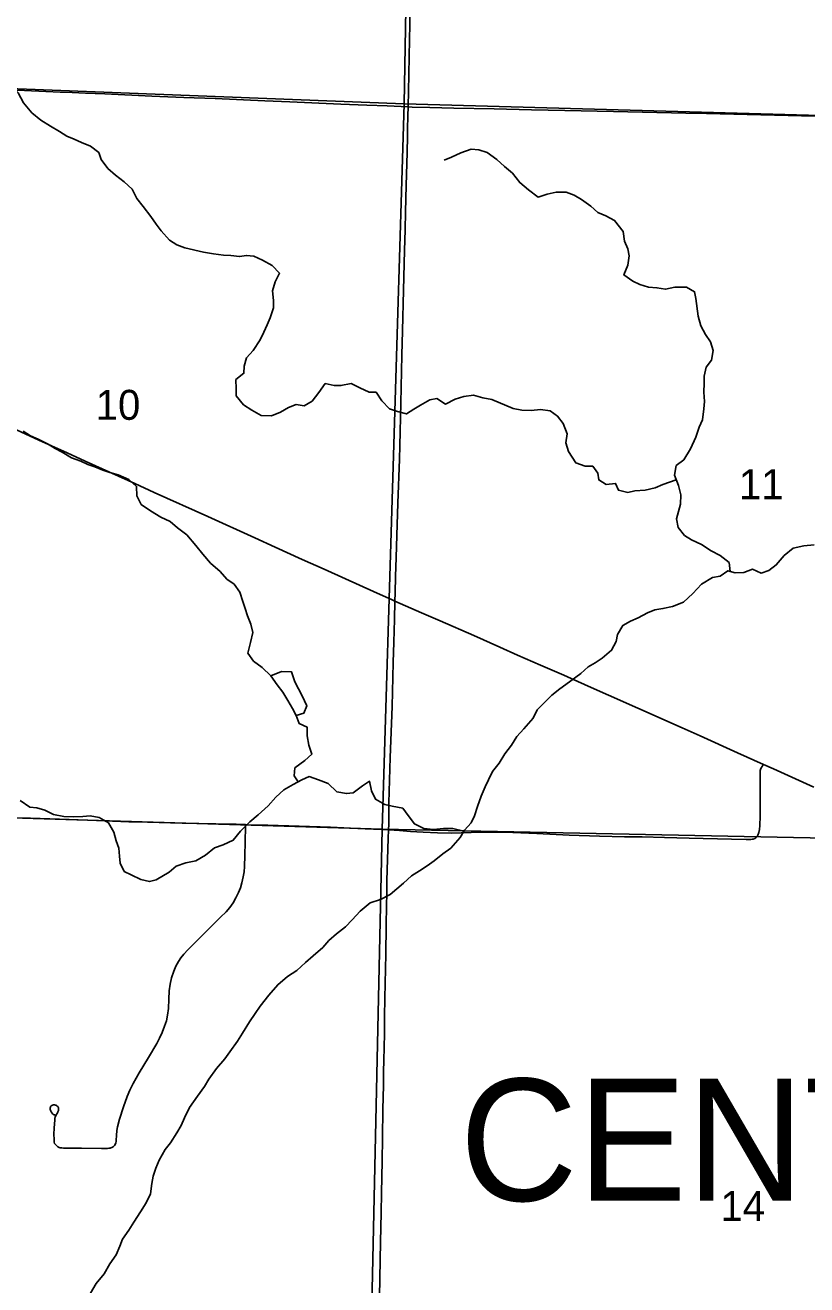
# Model space of a CAD drawing. Extents: x 0 to 34, y 0 to 22.
# Drawn here: x 3.245 to 4.336, y 17.97 to 19.729 of the extents above; entities that cross this region are included whole.
import ezdxf

# ---------------------------------------------------------------- set-up
doc = ezdxf.new("R2010")
doc.units = 0
for name, color, linetype in [('GM_X_Corporation', 7, 'Continuous'), ('GM_X_Minor_Lake', 7, 'Continuous'), ('GM_X_Minor_River', 7, 'Continuous'), ('GM_X_Section_Text', 7, 'Continuous'), ('GM_X_State_Route', 7, 'Continuous'), ('GM_X_Township_Road', 7, 'Continuous'), ('GM_X_Township_Text', 7, 'Continuous')]:
    doc.layers.add(name, color=color, linetype=linetype)

msp = doc.modelspace()

# ---------------------------------------------------------------- linework, layer by layer
at = {"layer": 'GM_X_Corporation'}
for points in [[(2.7647, 20.6164), (2.8121, 20.6157), (3.7914, 20.5987), (3.7742, 19.6197), (2.7554, 19.6589)], [(3.7914, 20.5987), (3.8107, 20.5986), (4.8123, 20.5837), (4.829, 20.5833), (4.8036, 19.5906), (3.7742, 19.6197)], [(2.7554, 19.6589), (3.7742, 19.6197), (3.7435, 18.6067), (2.7385, 18.6376)], [(3.7742, 19.6197), (4.8036, 19.5906), (4.7775, 18.5857), (3.7435, 18.6067)], [(2.7385, 18.6376), (3.7435, 18.6067), (3.7219, 17.5988), (2.7368, 17.6304)], [(3.7435, 18.6067), (4.7775, 18.5857), (4.7439, 17.5807), (3.7219, 17.5988)]]:
    msp.add_lwpolyline(points, close=True, dxfattribs=at)
at = {"layer": 'GM_X_Minor_Lake'}
for points in [[(3.6236, 18.7655), (3.6343, 18.7688), (3.6383, 18.7789), (3.6321, 18.7931), (3.6266, 18.8027), (3.6215, 18.8126), (3.6168, 18.8264), (3.6032, 18.827), (3.5883, 18.8209)], [(3.5883, 18.8209), (3.5972, 18.8082), (3.6049, 18.7982), (3.6119, 18.7863), (3.6185, 18.7751), (3.6236, 18.7655)]]:
    msp.add_lwpolyline(points, dxfattribs=at)
at = {"layer": 'GM_X_Minor_River'}
for points in [[(3.2669, 19.5968), (3.2546, 19.6069), (3.2427, 19.6208), (3.2354, 19.635), (3.2246, 19.6447), (3.2094, 19.6457), (3.1882, 19.6461), (3.1779, 19.6433), (3.1604, 19.6445)], [(4.1542, 19.0944), (4.1353, 19.0878), (4.1246, 19.0834), (4.1105, 19.0799), (4.0961, 19.079), (4.0866, 19.0769), (4.0734, 19.0799), (4.0694, 19.0894), (4.0561, 19.0882), (4.046, 19.0944), (4.0446, 19.1039), (4.0376, 19.1136), (4.027, 19.1134), (4.0138, 19.1182), (4.0035, 19.134), (4, 19.1462), (4.0017, 19.1587), (3.9963, 19.1732), (3.9882, 19.1832), (3.9781, 19.191), (3.9648, 19.1928), (3.9515, 19.1915), (3.9386, 19.1918), (3.9265, 19.1939), (3.8965, 19.2066), (3.884, 19.2088), (3.8712, 19.2128), (3.8575, 19.2108), (3.8456, 19.2072), (3.8322, 19.2003), (3.8199, 19.2081), (3.81, 19.2064), (3.7973, 19.199), (3.7877, 19.1932), (3.7774, 19.1865), (3.7649, 19.1898), (3.7536, 19.1938), (3.7432, 19.205), (3.7351, 19.2169), (3.7256, 19.2171), (3.7125, 19.2231), (3.7001, 19.229), (3.686, 19.2262), (3.6765, 19.2264), (3.664, 19.2289), (3.6551, 19.2166), (3.6458, 19.2042), (3.6346, 19.198), (3.6233, 19.1997), (3.6126, 19.1954), (3.6018, 19.1892), (3.5892, 19.1837), (3.5745, 19.1844), (3.5617, 19.1918), (3.5501, 19.1993), (3.5397, 19.212), (3.5399, 19.2215), (3.5394, 19.2344), (3.5506, 19.2433), (3.5508, 19.2531), (3.554, 19.2649), (3.5637, 19.2749), (3.5731, 19.2899), (3.5786, 19.3008), (3.583, 19.311), (3.5873, 19.3208), (3.5918, 19.3347), (3.592, 19.345), (3.5903, 19.3583), (3.594, 19.3711), (3.6003, 19.3831), (3.5899, 19.394), (3.5764, 19.4014), (3.5643, 19.407), (3.5541, 19.4079), (3.5446, 19.4062), (3.5325, 19.408), (3.5219, 19.4082), (3.5083, 19.41), (3.4943, 19.4125), (3.4679, 19.4183), (3.4569, 19.4227), (3.4468, 19.4294), (3.4349, 19.4421), (3.4279, 19.4517), (3.4205, 19.4621), (3.4098, 19.476), (3.4013, 19.4872), (3.3944, 19.5006), (3.3836, 19.5107), (3.3712, 19.52), (3.3608, 19.5293), (3.3515, 19.5417), (3.3479, 19.5516), (3.3364, 19.5605), (3.3239, 19.5657), (3.3134, 19.5701), (3.3033, 19.5745), (3.2931, 19.5807), (3.2804, 19.5882), (3.2669, 19.5968)], [(4.2293, 18.9667), (4.228, 18.9789), (4.2153, 18.9887), (4.203, 18.9954), (4.1895, 19.0044), (4.1756, 19.0107), (4.1658, 19.0166), (4.1569, 19.0278), (4.1545, 19.04), (4.157, 19.0505), (4.1602, 19.0607), (4.1605, 19.0736), (4.1573, 19.0866), (4.1515, 19.1011), (4.1541, 19.1144), (4.1648, 19.1225), (4.1739, 19.1379), (4.1814, 19.1541), (4.1862, 19.168), (4.1906, 19.1785), (4.1927, 19.1937), (4.1933, 19.2039), (4.1928, 19.2168), (4.1931, 19.2294), (4.1929, 19.2392), (4.1958, 19.2517), (4.2032, 19.2618), (4.2057, 19.275), (4.2018, 19.2873), (4.1951, 19.2973), (4.1885, 19.3095), (4.1846, 19.3229), (4.1813, 19.3476), (4.1796, 19.3571), (4.1683, 19.3634), (4.152, 19.3634), (4.1391, 19.3606), (4.127, 19.3627), (4.1153, 19.3637), (4.1032, 19.3674), (4.0934, 19.3721), (4.0811, 19.3807), (4.0866, 19.3942), (4.0884, 19.4075), (4.0867, 19.417), (4.082, 19.4277), (4.08, 19.4414), (4.0681, 19.4568), (4.0557, 19.4632), (4.0448, 19.4679), (4.0348, 19.4768), (4.0217, 19.4862), (4.0116, 19.4921), (4.0006, 19.4961), (3.9866, 19.496), (3.974, 19.4932), (3.9614, 19.4893), (3.948, 19.4994), (3.9357, 19.5095), (3.9253, 19.5226), (3.9145, 19.5319), (3.9037, 19.5416), (3.8902, 19.5517), (3.8785, 19.5554), (3.8676, 19.5564), (3.8534, 19.5513), (3.8404, 19.5451), (3.8301, 19.5411)], [(3.6264, 18.6729), (3.6205, 18.6813), (3.6218, 18.6923), (3.6357, 18.7027), (3.6454, 18.7116), (3.641, 18.7242), (3.639, 18.7372), (3.6389, 18.7489), (3.6276, 18.7541), (3.6236, 18.7655), (3.6185, 18.7751), (3.6119, 18.7863), (3.6049, 18.7982), (3.5972, 18.8082), (3.5883, 18.8209), (3.576, 18.8325), (3.564, 18.8411), (3.5559, 18.8526), (3.5596, 18.8674), (3.5629, 18.8813), (3.5601, 18.8928), (3.5554, 18.9046), (3.5522, 18.9149), (3.5493, 18.9245), (3.545, 18.9375), (3.5369, 18.9486), (3.5268, 18.956), (3.5175, 18.9665), (3.5041, 18.9781), (3.493, 18.9905), (3.4834, 19.0028), (3.4707, 19.0175), (3.4577, 19.0276), (3.4476, 19.0361), (3.4344, 19.0425), (3.4202, 19.0511), (3.4071, 19.0601), (3.4013, 19.072), (3.4008, 19.0852), (3.3899, 19.0949), (3.3749, 19.1017), (3.3636, 19.1049), (3.3538, 19.1078), (3.3425, 19.1126), (3.3327, 19.1158), (3.3229, 19.1205), (3.3101, 19.1253), (3.297, 19.1332), (3.2869, 19.1383), (3.2771, 19.1442), (3.2632, 19.1513), (3.2527, 19.156), (3.2422, 19.1623)], [(4.3465, 19.0036), (4.3324, 19.0024), (4.3175, 18.9989), (4.3048, 18.9889), (4.2936, 18.9758), (4.2832, 18.968), (4.2725, 18.964), (4.2605, 18.9696), (4.2483, 18.9649), (4.2361, 18.9647), (4.2263, 18.9676), (4.2152, 18.9602), (4.2049, 18.9581), (4.1895, 18.9486), (4.1772, 18.9359), (4.164, 18.9236), (4.1487, 18.9175), (4.1354, 18.9147), (4.1244, 18.913), (4.1141, 18.909), (4.101, 18.9017), (4.0903, 18.8973), (4.0796, 18.8911), (4.0722, 18.8787), (4.0704, 18.8689), (4.0638, 18.8565), (4.0507, 18.8454), (4.0407, 18.8391), (4.0311, 18.8332), (4.0207, 18.8239), (4.0053, 18.8125), (3.9918, 18.8025)], [(3.9918, 18.8025), (3.9803, 18.7936), (3.9694, 18.7828), (3.9601, 18.7731), (3.9542, 18.7618), (3.9411, 18.7469), (3.9317, 18.7361), (3.9243, 18.7241), (3.9146, 18.7117), (3.9068, 18.699), (3.8978, 18.6874), (3.8919, 18.6754), (3.8872, 18.6656), (3.8816, 18.6528), (3.8768, 18.6384), (3.8723, 18.6252), (3.868, 18.6155), (3.8587, 18.6054), (3.8524, 18.5949), (3.8393, 18.5803), (3.8281, 18.5722), (3.8162, 18.5626), (3.8062, 18.5556), (3.7958, 18.5485), (3.7843, 18.5416), (3.7735, 18.5311), (3.7546, 18.5156), (3.7412, 18.5086), (3.7267, 18.5036), (3.7128, 18.4921), (3.7016, 18.4801), (3.6926, 18.4701), (3.6796, 18.4605), (3.6691, 18.4512), (3.6606, 18.4415), (3.6471, 18.43), (3.6367, 18.4203), (3.6244, 18.4095), (3.6113, 18.401), (3.5978, 18.3895), (3.5854, 18.375), (3.5733, 18.3596), (3.5663, 18.3495), (3.5585, 18.3375), (3.5487, 18.3218), (3.5417, 18.3105), (3.5311, 18.2956), (3.5238, 18.2858), (3.5125, 18.2724), (3.5016, 18.2578), (3.4957, 18.2473), (3.486, 18.2338), (3.4747, 18.2181), (3.4676, 18.2038), (3.4632, 18.1929), (3.4569, 18.1828), (3.4479, 18.1689), (3.4405, 18.1592), (3.4323, 18.1445), (3.4275, 18.1332), (3.4239, 18.1223), (3.4222, 18.1121), (3.4204, 18.0973), (3.4141, 18.0849), (3.4063, 18.0721), (3.3969, 18.0579), (3.3898, 18.0467), (3.3813, 18.0343), (3.3773, 18.0245), (3.3721, 18.0121), (3.3635, 17.9997), (3.3553, 17.9858), (3.3444, 17.9724), (3.3366, 17.9589)], [(3.8578, 18.6039), (3.8424, 18.6076), (3.8292, 18.6075), (3.8151, 18.6062), (3.8015, 18.6076), (3.7887, 18.614), (3.7798, 18.6259), (3.7724, 18.6359), (3.7573, 18.6389), (3.7471, 18.641), (3.7344, 18.6484), (3.7285, 18.6603), (3.7261, 18.6736), (3.7162, 18.6674), (3.7031, 18.6574), (3.6936, 18.6564), (3.6804, 18.6589), (3.6684, 18.6706), (3.6549, 18.6757), (3.6417, 18.6802), (3.6314, 18.6754), (3.6191, 18.6692), (3.6061, 18.6615), (3.5953, 18.6515), (3.5844, 18.6395), (3.5705, 18.6265), (3.559, 18.6169), (3.5458, 18.6038), (3.5357, 18.5915), (3.5216, 18.585), (3.5093, 18.5806), (3.497, 18.5702), (3.4836, 18.5625), (3.4695, 18.5598), (3.4561, 18.5551), (3.4461, 18.5466), (3.4281, 18.5359), (3.4186, 18.5334), (3.4065, 18.5363), (3.3933, 18.543), (3.3836, 18.5478), (3.3777, 18.5593), (3.3768, 18.5692), (3.3759, 18.5802), (3.3723, 18.5905), (3.3691, 18.6027), (3.3617, 18.6154), (3.3486, 18.6228), (3.3358, 18.6254), (3.3259, 18.6244), (3.313, 18.6239), (3.299, 18.6246), (3.2846, 18.6271), (3.2726, 18.633), (3.2617, 18.6363), (3.2518, 18.6376), (3.2383, 18.6466)]]:
    msp.add_lwpolyline(points, dxfattribs=at)
at = {"layer": 'GM_X_State_Route'}
for points in [[(3.7791, 19.5842), (3.7795, 19.6029), (3.7797, 19.6154), (3.7807, 19.6601), (3.7811, 19.6862), (3.782, 19.731), (3.7827, 19.7683), (3.7834, 19.7947)], [(3.7613, 18.9251), (3.7617, 18.9369), (3.7621, 18.9593), (3.763, 18.986), (3.764, 19.017), (3.7655, 19.0618), (3.7676, 19.1233), (3.7681, 19.1419), (3.7697, 19.2015), (3.771, 19.2686), (3.7719, 19.3027), (3.7734, 19.3593), (3.7748, 19.4146), (3.7755, 19.4438), (3.7763, 19.4687), (3.7771, 19.5054), (3.7784, 19.5514), (3.7789, 19.5743), (3.7791, 19.5842)], [(3.1905, 19.1837), (3.2645, 19.1498), (3.3037, 19.1321), (3.3291, 19.1206), (3.3529, 19.1098), (3.3983, 19.0895), (3.4254, 19.077), (3.5002, 19.0432), (3.5659, 19.0133), (3.5942, 19.0004), (3.6321, 18.9834), (3.6627, 18.9696), (3.6922, 18.9564), (3.7313, 18.9386), (3.7574, 18.9268), (3.7613, 18.9251)], [(3.7397, 17.9535), (3.7412, 18.0306), (3.7421, 18.071), (3.7428, 18.099), (3.7434, 18.1431), (3.7439, 18.1755), (3.7447, 18.2159), (3.7452, 18.2488), (3.7455, 18.2681), (3.7459, 18.2836), (3.7467, 18.3209), (3.747, 18.3445), (3.7475, 18.3706), (3.7486, 18.4322), (3.7491, 18.4719), (3.7497, 18.5005), (3.7499, 18.5166), (3.7503, 18.5352), (3.7521, 18.5936), (3.7525, 18.6057), (3.7527, 18.6135), (3.7531, 18.6434), (3.7549, 18.7067), (3.7573, 18.7779), (3.7591, 18.8394), (3.7598, 18.868), (3.7607, 18.8997), (3.7613, 18.9251)], [(3.7613, 18.9251), (3.7984, 18.909), (3.8246, 18.8975), (3.8713, 18.8771), (3.9077, 18.8609), (3.9327, 18.8498), (3.9646, 18.8359), (3.997, 18.8216), (4.0312, 18.8066), (4.0595, 18.7939), (4.1004, 18.7758), (4.1623, 18.7482), (4.1873, 18.737), (4.2394, 18.7134), (4.2757, 18.6972), (4.2899, 18.6909), (4.346, 18.6654)]]:
    msp.add_lwpolyline(points, dxfattribs=at)
at = {"layer": 'GM_X_Township_Road'}
for points in [[(2.7597, 19.6587), (2.7706, 19.6585), (2.857, 19.655), (2.898, 19.6531), (2.9793, 19.6496), (3.0309, 19.6476), (3.0576, 19.6464), (3.1377, 19.6428), (3.2116, 19.6394), (3.2445, 19.638), (3.2739, 19.6368)], [(3.2739, 19.6368), (3.2942, 19.6359), (3.3109, 19.6352), (3.3296, 19.6343), (3.3563, 19.6333), (3.4221, 19.6302), (3.4668, 19.6286), (3.5103, 19.6268), (3.5799, 19.6236), (3.6146, 19.6222), (3.686, 19.6193), (3.7221, 19.6179), (3.7506, 19.6168), (3.7797, 19.6154)], [(3.7797, 19.6154), (3.7854, 19.6151), (3.8103, 19.6143), (3.8438, 19.6136), (3.8998, 19.6124), (3.952, 19.6114), (3.9986, 19.6101), (4.0663, 19.6088), (4.1676, 19.6064), (4.1962, 19.606), (4.3479, 19.6023), (4.4076, 19.6012), (4.4567, 19.5998), (4.5014, 19.5989), (4.5499, 19.5979), (4.5922, 19.597), (4.6785, 19.5948), (4.7152, 19.594), (4.8051, 19.5918)], [(4.2636, 18.5937), (4.2652, 18.5947), (4.2669, 18.5964), (4.2682, 18.5985), (4.2695, 18.602), (4.2703, 18.6063), (4.2709, 18.6118), (4.2712, 18.6249), (4.2713, 18.6448), (4.2711, 18.684), (4.2712, 18.6864), (4.2714, 18.6884), (4.2719, 18.6902), (4.2726, 18.6922), (4.2738, 18.6942), (4.2751, 18.6961), (4.2757, 18.6972)], [(2.7429, 18.6375), (2.7905, 18.6362), (2.8625, 18.634), (2.8992, 18.6329), (2.965, 18.6307), (3.0576, 18.628), (3.1067, 18.6266), (3.1402, 18.6254), (3.1726, 18.6244), (3.2067, 18.6232), (3.2527, 18.6221), (3.3068, 18.6204), (3.3447, 18.6187), (3.367, 18.6177), (3.39, 18.6171), (3.4161, 18.6164), (3.4646, 18.6152), (3.5112, 18.6142), (3.5398, 18.6136), (3.5527, 18.613)], [(3.3699, 18.1649), (3.3715, 18.1674), (3.372, 18.1689), (3.3723, 18.1704), (3.3723, 18.1726), (3.3725, 18.1791), (3.3731, 18.1859), (3.3741, 18.1908), (3.377, 18.2016), (3.3824, 18.2188), (3.3876, 18.2334), (3.3912, 18.2421), (3.3959, 18.2515), (3.4045, 18.2666), (3.4174, 18.2879), (3.4288, 18.3072), (3.4329, 18.3148), (3.4366, 18.3227), (3.4399, 18.3314), (3.4423, 18.3392), (3.444, 18.347), (3.4452, 18.3563), (3.4457, 18.3693), (3.4464, 18.3811), (3.4476, 18.3904), (3.4496, 18.3989), (3.4526, 18.4083), (3.4556, 18.4152), (3.4591, 18.4218), (3.4625, 18.427), (3.4667, 18.4323), (3.4721, 18.4384), (3.4942, 18.4602), (3.5181, 18.4837), (3.5256, 18.4912), (3.5308, 18.4974), (3.5354, 18.504), (3.5395, 18.511), (3.5431, 18.5182), (3.5456, 18.5246), (3.5478, 18.5317), (3.5497, 18.5402), (3.5507, 18.547), (3.5513, 18.5544), (3.5518, 18.5699), (3.5522, 18.5885), (3.5527, 18.611), (3.5527, 18.613)], [(3.5527, 18.613), (3.5553, 18.6129), (3.569, 18.6124), (3.5838, 18.6121), (3.6714, 18.6094), (3.6994, 18.6083), (3.7198, 18.6073), (3.7425, 18.6062)], [(3.7425, 18.6062), (3.7484, 18.606), (3.7525, 18.6057)], [(3.7525, 18.6057), (3.7676, 18.6047), (3.783, 18.6035), (3.801, 18.6025), (3.8207, 18.6016), (3.8409, 18.6012), (3.8539, 18.6016), (3.8818, 18.6026), (3.9005, 18.6026), (3.9259, 18.6019), (3.9595, 18.6007), (4.0048, 18.5983), (4.0471, 18.5969), (4.0819, 18.5962), (4.1067, 18.5958), (4.1378, 18.5951), (4.1719, 18.5943), (4.231, 18.5929), (4.2515, 18.5921), (4.2554, 18.5922), (4.2583, 18.5924), (4.2602, 18.5927), (4.2614, 18.5929), (4.2636, 18.5937)], [(3.2888, 18.1648), (3.2874, 18.1664), (3.2863, 18.1678), (3.2856, 18.1696), (3.2855, 18.1713), (3.2855, 18.1734), (3.2854, 18.1809), (3.2856, 18.189), (3.2865, 18.2008), (3.2868, 18.2028), (3.2873, 18.2051), (3.2881, 18.2066), (3.2887, 18.2079), (3.2899, 18.2097), (3.2905, 18.2108), (3.291, 18.2118), (3.2914, 18.213), (3.2917, 18.214), (3.2919, 18.2152), (3.2919, 18.2164), (3.2917, 18.2175), (3.2914, 18.2184), (3.2907, 18.2194), (3.29, 18.22), (3.2891, 18.2207), (3.288, 18.2212), (3.2873, 18.2214), (3.2864, 18.2216), (3.2849, 18.2216), (3.2834, 18.2213), (3.2826, 18.2209), (3.2815, 18.2203), (3.2808, 18.2194), (3.2804, 18.2186), (3.2801, 18.2177), (3.2802, 18.216), (3.2803, 18.2152), (3.2806, 18.2142), (3.281, 18.2131), (3.2815, 18.2121), (3.282, 18.2114), (3.2824, 18.2107), (3.2829, 18.21), (3.2836, 18.2094), (3.2848, 18.2084), (3.2854, 18.208), (3.2861, 18.2076), (3.2877, 18.2072)], [(3.2888, 18.1648), (3.2909, 18.1632), (3.2927, 18.1623), (3.294, 18.1618), (3.2963, 18.1615), (3.2989, 18.1614), (3.3237, 18.1611), (3.3516, 18.1607), (3.3602, 18.1609), (3.3621, 18.1611), (3.3639, 18.1613), (3.365, 18.1616), (3.3663, 18.1621), (3.368, 18.1631), (3.3699, 18.1649)]]:
    msp.add_lwpolyline(points, dxfattribs=at)

# ---------------------------------------------------------------- texts
at = {"layer": 'GM_X_Section_Text'}
for s, p in [('10', (3.3437, 19.1783)), ('11', (4.2416, 19.0675)), ('14', (4.2158, 18.0595))]:
    msp.add_text(s, height=0.04186, rotation=0, dxfattribs=at).set_placement(p)
at = {"layer": 'GM_X_Township_Text'}
msp.add_text('CENTER', height=0.17045, rotation=0, dxfattribs=at).set_placement((3.8518, 18.0877))

doc.saveas('drawing.dxf')
